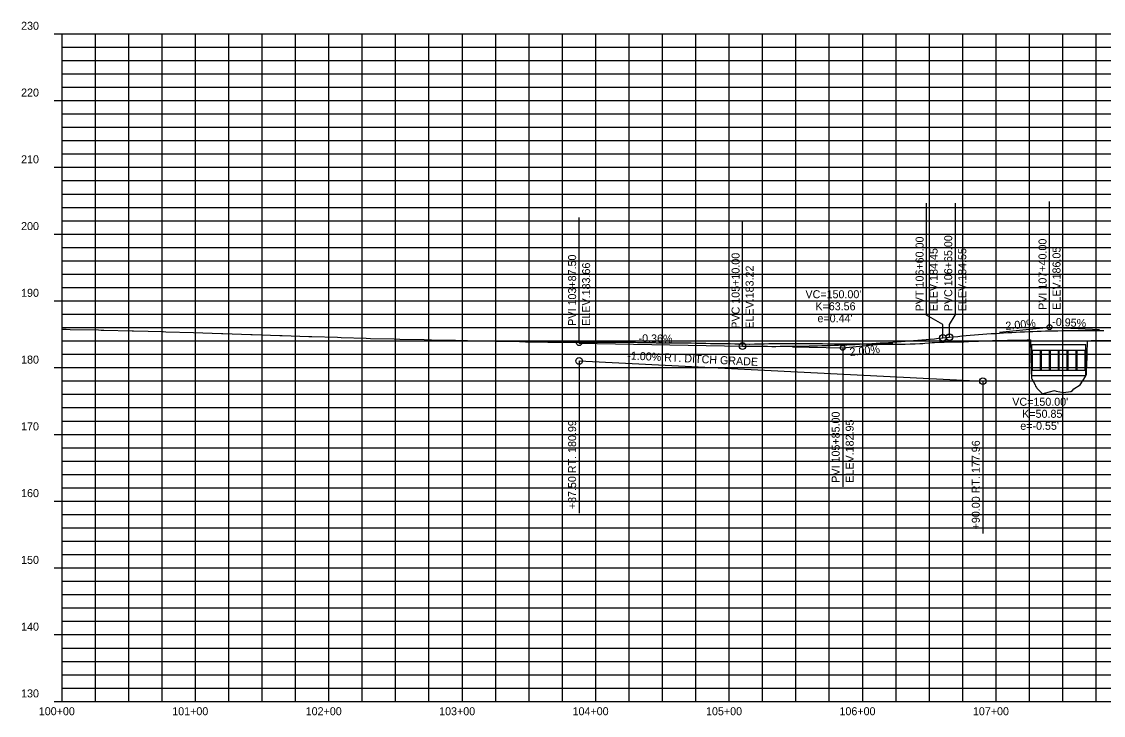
# Model space of a CAD drawing. Extents: x 1409239 to 1412142, y 1838831 to 1842626.
# Drawn here: x 1410882 to 1411693, y 1842106 to 1842626 of the extents above; entities that cross this region are included whole.
import ezdxf

# ---------------------------------------------------------------- set-up
doc = ezdxf.new("R2010")
doc.units = 0
for name, color, linetype in [('63', 7, 'Continuous'), ('R_Axis_Annotation', 7, 'Continuous'), ('R_Drainage', 7, 'Continuous'), ('R_Exist Surface', 7, 'Continuous'), ('R_Grid', 7, 'Continuous'), ('R_Grid Annot', 7, 'Continuous'), ('R_Grid_Minor', 7, 'Continuous'), ('R_Vert Alg', 7, 'Continuous'), ('R_Vert Alg Annot', 7, 'Continuous')]:
    doc.layers.add(name, color=color, linetype=linetype)

msp = doc.modelspace()

# ---------------------------------------------------------------- linework, layer by layer
at = {"layer": 'R_Drainage'}
for p, q in [((1411639.18, 1842360.79), (1411639.18, 1842384.13)), ((1411639.18, 1842384.13), (1411679.51, 1842384.13)), ((1411639.18, 1842379.96), (1411679.51, 1842379.96)), ((1411639.68, 1842364.96), (1411639.68, 1842379.96)), ((1411645.68, 1842364.96), (1411645.68, 1842379.96)), ((1411646.35, 1842364.96), (1411646.35, 1842379.96)), ((1411652.35, 1842364.96), (1411652.35, 1842379.96)), ((1411653.02, 1842364.96), (1411653.02, 1842379.96)), ((1411659.02, 1842364.96), (1411659.02, 1842379.96)), ((1411659.68, 1842364.96), (1411659.68, 1842379.96)), ((1411665.68, 1842364.96), (1411665.68, 1842379.96)), ((1411666.34, 1842364.96), (1411666.34, 1842379.96)), ((1411672.34, 1842364.96), (1411672.34, 1842379.96)), ((1411673.01, 1842364.96), (1411673.01, 1842379.96)), ((1411679.01, 1842364.96), (1411679.01, 1842379.96)), ((1411679.51, 1842360.79), (1411679.51, 1842384.13)), ((1411639.18, 1842364.96), (1411679.51, 1842364.96)), ((1411639.18, 1842360.79), (1411679.51, 1842360.79))]:
    msp.add_line(p, q, dxfattribs=at)
at = {"layer": 'R_Exist Surface'}
msp.add_lwpolyline([(1410912.35, 1842395.65), (1410915.57, 1842395.56), (1410918.56, 1842395.47), (1410939.81, 1842395.01), (1410941.76, 1842394.96), (1410943.58, 1842394.92), (1410964.98, 1842394.46), (1410965.95, 1842394.44), (1410987.96, 1842393.78), (1410988.05, 1842393.77), (1410990.19, 1842393.71), (1411010.91, 1842392.98), (1411031.92, 1842392.33), (1411032.89, 1842392.3), (1411053.73, 1842391.65), (1411054.87, 1842391.61), (1411075.6, 1842390.9), (1411077.29, 1842390.85), (1411097.4, 1842390.16), (1411099.67, 1842390.09), (1411118.73, 1842389.49), (1411121.55, 1842389.39), (1411140.22, 1842388.8), (1411143.43, 1842388.7), (1411161.18, 1842388.35), (1411165.44, 1842388.17), (1411183.85, 1842387.84), (1411189.14, 1842387.66), (1411207.1, 1842387.32), (1411211.47, 1842387.2), (1411216.1, 1842387.09), (1411233.82, 1842386.75), (1411237.92, 1842386.69), (1411255.15, 1842386.28), (1411259.55, 1842386.22), (1411276.49, 1842385.82), (1411295.17, 1842385.89), (1411298.64, 1842385.89), (1411299.85, 1842385.9), (1411303.5, 1842385.91), (1411307.15, 1842385.91), (1411310.8, 1842385.9), (1411314.45, 1842385.88), (1411318.06, 1842385.85), (1411318.09, 1842385.84), (1411320.8, 1842385.8), (1411321.74, 1842385.81), (1411325.39, 1842385.82), (1411329.04, 1842385.83), (1411332.69, 1842385.83), (1411336.34, 1842385.81), (1411338.85, 1842385.8), (1411339.98, 1842385.78), (1411342.06, 1842385.74), (1411343.63, 1842385.72), (1411347.28, 1842385.67), (1411350.93, 1842385.6), (1411354.58, 1842385.53), (1411357.6, 1842385.46), (1411358.23, 1842385.44), (1411361.88, 1842385.3), (1411363.36, 1842385.24), (1411365.52, 1842385.27), (1411369.17, 1842385.32), (1411372.82, 1842385.36), (1411376.47, 1842385.38), (1411376.76, 1842385.38), (1411380.12, 1842385.32), (1411382.88, 1842385.26), (1411383.77, 1842385.24), (1411387.41, 1842385.15), (1411390.48, 1842385.06), (1411391.06, 1842385.06), (1411394.71, 1842385), (1411398.36, 1842384.93), (1411402.01, 1842384.84), (1411402.31, 1842384.83), (1411405.66, 1842384.84), (1411408.43, 1842384.84), (1411409.3, 1842384.83), (1411412.95, 1842384.79), (1411416.6, 1842384.72), (1411420.25, 1842384.64), (1411422.02, 1842384.59), (1411423.9, 1842384.56), (1411427.33, 1842384.48), (1411427.55, 1842384.48), (1411431.2, 1842384.56), (1411434.84, 1842384.62), (1411435.99, 1842384.64), (1411438.49, 1842384.7), (1411442.14, 1842384.78), (1411445.79, 1842384.85), (1411449.44, 1842384.9), (1411449.66, 1842384.9), (1411453.09, 1842384.88), (1411456.73, 1842384.85), (1411458.43, 1842384.83), (1411460.38, 1842384.83), (1411464.03, 1842384.83), (1411467.68, 1842384.8), (1411471.33, 1842384.77), (1411472.47, 1842384.75), (1411474.98, 1842384.76), (1411478.62, 1842384.76), (1411479.92, 1842384.76), (1411482.27, 1842384.74), (1411485.92, 1842384.69), (1411489.57, 1842384.63), (1411490.75, 1842384.6), (1411493.22, 1842384.65), (1411496.44, 1842384.71), (1411496.87, 1842384.7), (1411500.52, 1842384.63), (1411504.16, 1842384.53), (1411505.13, 1842384.5), (1411507.81, 1842384.52), (1411511.13, 1842384.52), (1411511.46, 1842384.51), (1411515.11, 1842384.36), (1411518.76, 1842384.2), (1411519.54, 1842384.16), (1411522.41, 1842384.26), (1411525.1, 1842384.34), (1411526.05, 1842384.35), (1411529.7, 1842384.35), (1411533.35, 1842384.33), (1411537, 1842384.29), (1411537.7, 1842384.28), (1411540.65, 1842384.32), (1411544.16, 1842384.35), (1411544.3, 1842384.35), (1411547.95, 1842384.55), (1411551.59, 1842384.73), (1411555.24, 1842384.88), (1411557.31, 1842384.96), (1411558.89, 1842385.08), (1411562.54, 1842385.36), (1411564.53, 1842385.51), (1411566.19, 1842385.62), (1411569.84, 1842385.87), (1411571.19, 1842385.95), (1411573.48, 1842385.98), (1411577.13, 1842386.01), (1411580.78, 1842386.03), (1411584.43, 1842386.03), (1411584.94, 1842386.03), (1411588.08, 1842386.18), (1411591.73, 1842386.34), (1411595.37, 1842386.49), (1411599.02, 1842386.62), (1411602.67, 1842386.74), (1411603.05, 1842386.75), (1411606.32, 1842386.92), (1411606.51, 1842386.93), (1411609.69, 1842387.08), (1411609.97, 1842387.09), (1411613.62, 1842387.15), (1411617.27, 1842387.2), (1411620.91, 1842387.25), (1411624.56, 1842387.28), (1411628.19, 1842387.31), (1411628.21, 1842387.32), (1411629.05, 1842387.41), (1411631.86, 1842387.47), (1411635.51, 1842387.56), (1411638.15, 1842387.61), (1411638.63, 1842364.41), (1411638.88, 1842359.02), (1411639.16, 1842358.49), (1411641.52, 1842353.96), (1411641.94, 1842353.01), (1411642.5, 1842351.81), (1411642.8, 1842351.51), (1411647.06, 1842347.28), (1411648.52, 1842347.66), (1411656.16, 1842349.72), (1411657.33, 1842349.19), (1411662.9, 1842348.09), (1411662.91, 1842348.09), (1411668.4, 1842348.99), (1411669.5, 1842349.66), (1411670.46, 1842350.92), (1411675.42, 1842353.87), (1411679.28, 1842360.07), (1411679.99, 1842361.65), (1411679.99, 1842361.65), (1411680.19, 1842366.68), (1411680.22, 1842366.86), (1411680.92, 1842386.94), (1411683.57, 1842387.01), (1411691.21, 1842386.99), (1411704.14, 1842387.25)], dxfattribs=at)
at = {"layer": 'R_Grid'}
for p, q in [((1410912.35, 1842116.81), (1410912.35, 1842616.81)), ((1410912.35, 1842616.81), (1412112.35, 1842616.81)), ((1410912.35, 1842616.81), (1412112.35, 1842616.81)), ((1411012.35, 1842116.81), (1411012.35, 1842616.81)), ((1411112.35, 1842116.81), (1411112.35, 1842616.81)), ((1411212.35, 1842116.81), (1411212.35, 1842616.81)), ((1411312.35, 1842116.81), (1411312.35, 1842616.81)), ((1411412.35, 1842116.81), (1411412.35, 1842616.81)), ((1411512.35, 1842116.81), (1411512.35, 1842616.81)), ((1411612.35, 1842116.81), (1411612.35, 1842616.81)), ((1410912.35, 1842566.81), (1412112.35, 1842566.81)), ((1410912.35, 1842516.81), (1412112.35, 1842516.81)), ((1410912.35, 1842466.81), (1412112.35, 1842466.81)), ((1410912.35, 1842416.81), (1412112.35, 1842416.81)), ((1410912.35, 1842366.81), (1412112.35, 1842366.81)), ((1410912.35, 1842316.81), (1412112.35, 1842316.81)), ((1410912.35, 1842266.81), (1412112.35, 1842266.81)), ((1410912.35, 1842216.81), (1412112.35, 1842216.81)), ((1410912.35, 1842166.81), (1412112.35, 1842166.81)), ((1410912.35, 1842116.81), (1412112.35, 1842116.81))]:
    msp.add_line(p, q, dxfattribs=at)
at = {"layer": 'R_Grid Annot'}
for p, q in [((1410906.35, 1842616.81), (1410912.35, 1842616.81)), ((1410906.35, 1842616.81), (1410912.35, 1842616.81)), ((1410912.35, 1842606.81), (1410915.35, 1842606.81)), ((1410912.35, 1842596.81), (1410915.35, 1842596.81)), ((1410912.35, 1842586.81), (1410915.35, 1842586.81)), ((1410912.35, 1842576.81), (1410915.35, 1842576.81)), ((1410906.35, 1842566.81), (1410912.35, 1842566.81)), ((1410912.35, 1842556.81), (1410915.35, 1842556.81)), ((1410912.35, 1842546.81), (1410915.35, 1842546.81)), ((1410912.35, 1842536.81), (1410915.35, 1842536.81)), ((1410912.35, 1842526.81), (1410915.35, 1842526.81)), ((1410906.35, 1842516.81), (1410912.35, 1842516.81)), ((1410912.35, 1842506.81), (1410915.35, 1842506.81)), ((1410912.35, 1842496.81), (1410915.35, 1842496.81)), ((1410912.35, 1842486.81), (1410915.35, 1842486.81)), ((1410912.35, 1842476.81), (1410915.35, 1842476.81)), ((1410906.35, 1842466.81), (1410912.35, 1842466.81)), ((1410912.35, 1842456.81), (1410915.35, 1842456.81)), ((1410912.35, 1842446.81), (1410915.35, 1842446.81)), ((1410912.35, 1842436.81), (1410915.35, 1842436.81)), ((1410912.35, 1842426.81), (1410915.35, 1842426.81)), ((1410906.35, 1842416.81), (1410912.35, 1842416.81)), ((1410912.35, 1842406.81), (1410915.35, 1842406.81)), ((1410912.35, 1842396.81), (1410915.35, 1842396.81)), ((1410912.35, 1842386.81), (1410915.35, 1842386.81)), ((1410912.35, 1842376.81), (1410915.35, 1842376.81)), ((1410906.35, 1842366.81), (1410912.35, 1842366.81)), ((1410912.35, 1842356.81), (1410915.35, 1842356.81)), ((1410912.35, 1842346.81), (1410915.35, 1842346.81)), ((1410912.35, 1842336.81), (1410915.35, 1842336.81)), ((1410912.35, 1842326.81), (1410915.35, 1842326.81)), ((1410906.35, 1842316.81), (1410912.35, 1842316.81)), ((1410912.35, 1842306.81), (1410915.35, 1842306.81)), ((1410912.35, 1842296.81), (1410915.35, 1842296.81)), ((1410912.35, 1842286.81), (1410915.35, 1842286.81)), ((1410912.35, 1842276.81), (1410915.35, 1842276.81)), ((1410906.35, 1842266.81), (1410912.35, 1842266.81)), ((1410912.35, 1842256.81), (1410915.35, 1842256.81)), ((1410912.35, 1842246.81), (1410915.35, 1842246.81)), ((1410912.35, 1842236.81), (1410915.35, 1842236.81)), ((1410912.35, 1842226.81), (1410915.35, 1842226.81)), ((1410906.35, 1842216.81), (1410912.35, 1842216.81)), ((1410912.35, 1842206.81), (1410915.35, 1842206.81)), ((1410912.35, 1842196.81), (1410915.35, 1842196.81)), ((1410912.35, 1842186.81), (1410915.35, 1842186.81)), ((1410912.35, 1842176.81), (1410915.35, 1842176.81)), ((1410906.35, 1842166.81), (1410912.35, 1842166.81)), ((1410912.35, 1842156.81), (1410915.35, 1842156.81)), ((1410912.35, 1842146.81), (1410915.35, 1842146.81)), ((1410912.35, 1842136.81), (1410915.35, 1842136.81)), ((1410912.35, 1842126.81), (1410915.35, 1842126.81)), ((1410906.35, 1842116.81), (1410912.35, 1842116.81))]:
    msp.add_line(p, q, dxfattribs=at)
at = {"layer": 'R_Grid_Minor'}
for p, q in [((1410937.35, 1842116.81), (1410937.35, 1842616.81)), ((1410962.35, 1842116.81), (1410962.35, 1842616.81)), ((1410987.35, 1842116.81), (1410987.35, 1842616.81)), ((1411037.35, 1842116.81), (1411037.35, 1842616.81)), ((1411062.35, 1842116.81), (1411062.35, 1842616.81)), ((1411087.35, 1842116.81), (1411087.35, 1842616.81)), ((1411137.35, 1842116.81), (1411137.35, 1842616.81)), ((1411162.35, 1842116.81), (1411162.35, 1842616.81)), ((1411187.35, 1842116.81), (1411187.35, 1842616.81)), ((1411237.35, 1842116.81), (1411237.35, 1842616.81)), ((1411262.35, 1842116.81), (1411262.35, 1842616.81)), ((1411287.35, 1842116.81), (1411287.35, 1842616.81)), ((1411337.35, 1842116.81), (1411337.35, 1842616.81)), ((1411362.35, 1842116.81), (1411362.35, 1842616.81)), ((1411387.35, 1842116.81), (1411387.35, 1842616.81)), ((1411437.35, 1842116.81), (1411437.35, 1842616.81)), ((1411462.35, 1842116.81), (1411462.35, 1842616.81)), ((1411487.35, 1842116.81), (1411487.35, 1842616.81)), ((1411537.35, 1842116.81), (1411537.35, 1842616.81)), ((1411562.35, 1842116.81), (1411562.35, 1842616.81)), ((1411587.35, 1842116.81), (1411587.35, 1842616.81)), ((1411637.35, 1842116.81), (1411637.35, 1842616.81)), ((1411662.35, 1842116.81), (1411662.35, 1842616.81)), ((1411687.35, 1842116.81), (1411687.35, 1842616.81)), ((1410912.35, 1842606.81), (1412112.35, 1842606.81)), ((1410912.35, 1842596.81), (1412112.35, 1842596.81)), ((1410912.35, 1842586.81), (1412112.35, 1842586.81)), ((1410912.35, 1842576.81), (1412112.35, 1842576.81)), ((1410912.35, 1842556.81), (1412112.35, 1842556.81)), ((1410912.35, 1842546.81), (1412112.35, 1842546.81)), ((1410912.35, 1842536.81), (1412112.35, 1842536.81)), ((1410912.35, 1842526.81), (1412112.35, 1842526.81)), ((1410912.35, 1842506.81), (1412112.35, 1842506.81)), ((1410912.35, 1842496.81), (1412112.35, 1842496.81)), ((1410912.35, 1842486.81), (1412112.35, 1842486.81)), ((1410912.35, 1842476.81), (1412112.35, 1842476.81)), ((1410912.35, 1842456.81), (1412112.35, 1842456.81)), ((1410912.35, 1842446.81), (1412112.35, 1842446.81)), ((1410912.35, 1842436.81), (1412112.35, 1842436.81)), ((1410912.35, 1842426.81), (1412112.35, 1842426.81)), ((1410912.35, 1842406.81), (1412112.35, 1842406.81)), ((1410912.35, 1842396.81), (1412112.35, 1842396.81)), ((1410912.35, 1842386.81), (1412112.35, 1842386.81)), ((1410912.35, 1842376.81), (1412112.35, 1842376.81)), ((1410912.35, 1842356.81), (1412112.35, 1842356.81)), ((1410912.35, 1842346.81), (1412112.35, 1842346.81)), ((1410912.35, 1842336.81), (1412112.35, 1842336.81)), ((1410912.35, 1842326.81), (1412112.35, 1842326.81)), ((1410912.35, 1842306.81), (1412112.35, 1842306.81)), ((1410912.35, 1842296.81), (1412112.35, 1842296.81)), ((1410912.35, 1842286.81), (1412112.35, 1842286.81)), ((1410912.35, 1842276.81), (1412112.35, 1842276.81)), ((1410912.35, 1842256.81), (1412112.35, 1842256.81)), ((1410912.35, 1842246.81), (1412112.35, 1842246.81)), ((1410912.35, 1842236.81), (1412112.35, 1842236.81)), ((1410912.35, 1842226.81), (1412112.35, 1842226.81)), ((1410912.35, 1842206.81), (1412112.35, 1842206.81)), ((1410912.35, 1842196.81), (1412112.35, 1842196.81)), ((1410912.35, 1842186.81), (1412112.35, 1842186.81)), ((1410912.35, 1842176.81), (1412112.35, 1842176.81)), ((1410912.35, 1842156.81), (1412112.35, 1842156.81)), ((1410912.35, 1842146.81), (1412112.35, 1842146.81)), ((1410912.35, 1842136.81), (1412112.35, 1842136.81)), ((1410912.35, 1842126.81), (1412112.35, 1842126.81))]:
    msp.add_line(p, q, dxfattribs=at)
at = {"layer": 'R_Vert Alg'}
for p, q in [((1411299.85, 1842385.14), (1411422.35, 1842382.94)), ((1411572.35, 1842389.09), (1411577.35, 1842389.59)), ((1411299.85, 1842371.76), (1411602.35, 1842356.64))]:
    msp.add_line(p, q, dxfattribs=at)
for points in [[(1411577.35, 1842389.59), (1411580.48, 1842389.89), (1411583.6, 1842390.19), (1411586.73, 1842390.48), (1411589.85, 1842390.76), (1411592.98, 1842391.03), (1411596.1, 1842391.29), (1411599.23, 1842391.54), (1411602.35, 1842391.78), (1411605.48, 1842392.01), (1411608.6, 1842392.23), (1411611.73, 1842392.44), (1411614.85, 1842392.64), (1411617.98, 1842392.84), (1411621.1, 1842393.02), (1411624.23, 1842393.19), (1411627.35, 1842393.36), (1411630.48, 1842393.51), (1411633.6, 1842393.65), (1411636.73, 1842393.79), (1411639.85, 1842393.91), (1411642.98, 1842394.03), (1411646.1, 1842394.14), (1411649.23, 1842394.23), (1411655.48, 1842394.4), (1411658.6, 1842394.46), (1411661.73, 1842394.52), (1411664.85, 1842394.57), (1411667.98, 1842394.61), (1411671.1, 1842394.64), (1411674.23, 1842394.66), (1411677.35, 1842394.67), (1411680.48, 1842394.67), (1411683.6, 1842394.66), (1411686.73, 1842394.64), (1411689.85, 1842394.61), (1411692.98, 1842394.57)], [(1411422.35, 1842382.94), (1411425.48, 1842382.88), (1411428.6, 1842382.84), (1411431.73, 1842382.8), (1411434.85, 1842382.77), (1411437.98, 1842382.75), (1411441.1, 1842382.74), (1411444.23, 1842382.73), (1411447.35, 1842382.73), (1411450.48, 1842382.74), (1411453.6, 1842382.76), (1411456.73, 1842382.78), (1411459.85, 1842382.81), (1411462.98, 1842382.85), (1411466.1, 1842382.9), (1411469.23, 1842382.96), (1411472.35, 1842383.02), (1411475.48, 1842383.09), (1411478.6, 1842383.17), (1411481.73, 1842383.25), (1411484.85, 1842383.35), (1411487.98, 1842383.45), (1411491.1, 1842383.56), (1411494.23, 1842383.67), (1411500.48, 1842383.93), (1411503.6, 1842384.07), (1411506.73, 1842384.22), (1411509.85, 1842384.37), (1411512.98, 1842384.53), (1411516.1, 1842384.71), (1411519.23, 1842384.88), (1411522.35, 1842385.07), (1411525.48, 1842385.26), (1411528.6, 1842385.46), (1411531.73, 1842385.67), (1411534.85, 1842385.89), (1411537.98, 1842386.11), (1411541.1, 1842386.34), (1411544.23, 1842386.58), (1411547.35, 1842386.83), (1411550.48, 1842387.09), (1411553.6, 1842387.35), (1411556.73, 1842387.62), (1411559.85, 1842387.9), (1411562.98, 1842388.18), (1411566.1, 1842388.48), (1411569.23, 1842388.78), (1411572.35, 1842389.09)]]:
    msp.add_lwpolyline(points, dxfattribs=at)
at = {"layer": 'R_Vert Alg Annot'}
for p, q in [((1411652.35, 1842407.09), (1411652.35, 1842491.09)), ((1411560.24, 1842405.98), (1411560.24, 1842489.98)), ((1411581.7, 1842490.05), (1411581.7, 1842406.05)), ((1411299.85, 1842395.14), (1411299.85, 1842479.14)), ((1411422.35, 1842392.94), (1411422.35, 1842476.94)), ((1411572.35, 1842399.09), (1411560.24, 1842405.98)), ((1411577.35, 1842399.12), (1411581.7, 1842406.05)), ((1411652.35, 1842397.09), (1411652.35, 1842407.09)), ((1411299.85, 1842385.14), (1411299.85, 1842395.14)), ((1411572.35, 1842389.09), (1411572.35, 1842399.09)), ((1411577.35, 1842389.59), (1411577.35, 1842399.12)), ((1411614.85, 1842393.34), (1411652.35, 1842397.09)), ((1411652.35, 1842397.09), (1411689.85, 1842395.3)), ((1411422.35, 1842382.94), (1411422.35, 1842392.94)), ((1411497.35, 1842381.59), (1411534.85, 1842385.34)), ((1411459.85, 1842382.26), (1411497.35, 1842381.59)), ((1411497.35, 1842381.59), (1411497.35, 1842361.59)), ((1411299.85, 1842371.76), (1411299.85, 1842341.76)), ((1411497.35, 1842361.59), (1411497.35, 1842277.59)), ((1411602.35, 1842356.64), (1411602.35, 1842326.64)), ((1411299.85, 1842341.76), (1411299.85, 1842257.76)), ((1411602.35, 1842326.64), (1411602.35, 1842242.64))]:
    msp.add_line(p, q, dxfattribs=at)
for centre, radius in [((1411652.35, 1842397.09), 1.85), ((1411299.85, 1842385.14), 1.85), ((1411422.35, 1842382.94), 2.5), ((1411572.35, 1842389.09), 2.5), ((1411577.35, 1842389.59), 2.5), ((1411497.35, 1842381.59), 1.85), ((1411299.85, 1842371.76), 2.5), ((1411602.35, 1842356.64), 2.5)]:
    msp.add_circle(centre, radius, dxfattribs=at)

# ---------------------------------------------------------------- texts
at = {"layer": '63'}
msp.add_text('-', height=0.0001, dxfattribs=at).set_placement((1410912.35, 1842116.81))
at = {"layer": 'R_Axis_Annotation'}
for s, p in [('230', (1410881.68, 1842619.81)), ('230', (1410881.68, 1842619.81)), ('220', (1410881.68, 1842569.81)), ('210', (1410881.68, 1842519.81)), ('200', (1410881.68, 1842469.81)), ('190', (1410881.68, 1842419.81)), ('180', (1410881.68, 1842369.81)), ('170', (1410881.68, 1842319.81)), ('160', (1410881.68, 1842269.81)), ('150', (1410881.68, 1842219.81)), ('140', (1410881.68, 1842169.81)), ('130', (1410881.68, 1842119.81)), ('100+00', (1410894.95, 1842106.46)), ('101+00', (1410994.95, 1842106.46)), ('102+00', (1411094.95, 1842106.46)), ('103+00', (1411194.95, 1842106.46)), ('104+00', (1411294.95, 1842106.46)), ('105+00', (1411394.95, 1842106.46)), ('106+00', (1411494.95, 1842106.46)), ('107+00', (1411594.95, 1842106.46))]:
    msp.add_text(s, height=6, dxfattribs=at).set_placement(p)
at = {"layer": 'R_Vert Alg Annot'}
for s, rotation, p in [('PVT 106+60.00', 90, (1411557.99, 1842408.98)), ('PVC 106+65.00', 90, (1411579.45, 1842409.05)), ('PVI 107+40.00', 90, (1411650.1, 1842410.09)), ('PVI 103+87.50', 90, (1411297.6, 1842398.14)), ('PVC 105+10.00', 90, (1411420.1, 1842395.94)), ('ELEV.184.45', 90, (1411568.49, 1842408.98)), ('ELEV.184.55', 90, (1411589.95, 1842409.05)), ('ELEV.186.05', 90, (1411660.6, 1842410.09)), ('ELEV.183.66', 90, (1411308.1, 1842398.14)), ('ELEV.183.22', 90, (1411430.6, 1842395.94)), ('2.00%', 5.71059, (1411619.67, 1842395)), ('-0.95%', 357.28049, (1411654.26, 1842398.23)), ('-0.36%', 358.96879, (1411344.33, 1842385.84)), ('-1.00% RT. DITCH GRADE', 357.13759, (1411335.83, 1842372.97)), ('2.00%', 5.71059, (1411502.85, 1842375.51)), ('PVI 105+85.00', 90, (1411495.1, 1842280.59)), ('+87.50 RT. 180.99', 90, (1411297.6, 1842260.76)), ('ELEV.182.95', 90, (1411505.6, 1842280.59)), ('+90.00 RT. 177.96', 90, (1411600.1, 1842245.64))]:
    msp.add_text(s, height=6, rotation=rotation, dxfattribs=at).set_placement(p)
for s, p in [("VC=150.00'", (1411469.45, 1842418.75)), ('K=63.56', (1411476.88, 1842409.75)), ("e=0.44'", (1411478.45, 1842400.75)), ("VC=150.00'", (1411624.45, 1842338.22)), ('K=50.85', (1411631.89, 1842329.22)), ("e=-0.55'", (1411630.45, 1842320.22))]:
    msp.add_text(s, height=6, dxfattribs=at).set_placement(p)

doc.saveas('drawing.dxf')
